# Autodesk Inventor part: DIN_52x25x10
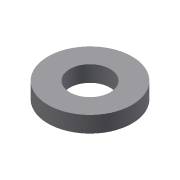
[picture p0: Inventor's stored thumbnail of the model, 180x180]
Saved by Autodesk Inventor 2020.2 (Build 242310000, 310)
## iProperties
Created: 2014-10
Part Number: DIN_52x25x10
Material: Ogólny
Document SubType Name: Modeling
Designer: F.Stasiak
Density: 1 g/cm^3
Appearance: Domyślna
Catalog Web Link: www.expertbooks.pl
Manager: www.cadconsulting.pl
Company: Fabian Stasiak CAD Consulting
Author: F.Stasiak
Subject: Zbiór ćwiczeń. Autodesk Inventor 2020. Kurs Professional
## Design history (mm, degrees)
sketch "Szkic1"
  geometry: C1 r 26 at (0, 0); C2 r 12.5 at (0, 0); 1 further point
  constraints: 2 centre point, 2 coincident
  dimensions: "d0" = 52 diameter of C1; "d1" = 25 diameter of C2
extrude "Wyciągnięcie proste1" new body sketch "Szkic1" distance "d2" = 10; taper "d3" = 0 deg
node "Bryła1"
